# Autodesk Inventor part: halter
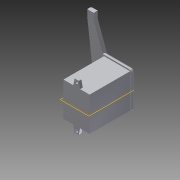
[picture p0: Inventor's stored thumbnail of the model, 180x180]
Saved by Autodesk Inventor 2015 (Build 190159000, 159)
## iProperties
Created: 2015-03
Part Number: halter
Material: PVC, hart
Document SubType Name: Modeling
Designer: Andreas
Density: 1.29 g/cm^3
Appearance: Glatt - weiß
Author: Andreas
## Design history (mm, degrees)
sketch "Skizze1"
  geometry: L1 (0, 0)-(20, 0); L2 (20, 0)-(20, -26); L3 (20, -26)-(0, -26); L4 (0, -26)-(0, 0); 3 further points
  constraints: 8 end point, 2 horizontal, 2 point on line, 1 midpoint, 1 perpendicular
  dimensions: "d1" = 26 distance of L1.end L2.end; "d2" = 20 distance of L2.end L3.end; "d3" = 26 distance of L3.end L1.start (derived); "d11" = 7.5 distance of L1.start point (7.5, 0)
extrude "Extrusion1" new body sketch "Skizze1" distance "d16" = 31; taper "d17" = 0 deg
sketch "Skizze2"
  geometry: L1 (-8.295, 5)-(-11.295, 5); L2 (-7.277, 0)-(-8.295, 5); L3 (-12.5, 0)-(-11.541, 4.799); L4 (-20, 0)-(0, 0) reference; L5 (-7.277, 0)-(-12.5, 0); A1 r 0.25 centre (-8.295, 4.75) between (-8.295, 5) and (-8.295, 5); A2 r 0.25 centre (-11.295, 4.75) between (-11.295, 5) and (-11.541, 4.799); 1 further point
  constraints: 8 end point, 4 point on circle, 3 tangent, 2 centre point, 1 collinear, 1 midpoint, 1 point on line, 1 other
  dimensions: "d18" = 3 distance of L1.start L1.end; "d19" = 5 vertical distance of L3.start L1.end; "d21" = 0.5 diameter of A2; "d26" = 7.5 distance of L4.start L3.start; "d27" = 5 vertical distance of L2.start L2.end
extrude "Extrusion2" join sketch "Skizze2" distance "d28" = 2; taper "d29" = 0 deg
fillet "Rundung1" dims "d30" = 0.5
hole "Bohrung1" diameter "d33" = 2; stored, may be unused: countersink angle "d37" = 90 deg, drill point angle "d39" = 118 deg; dims "d31" = 10, "d32" = 10, "d34" = 6, "d35" = 4, "d36" = 2, "d38" = 8
workplane "Arbeitsebene1"
mirror "Spiegeln1"
sketch "Skizze3"
  geometry: L1 (-21, -1)-(1, -1); L2 (1, -1)-(1, 27); L3 (1, 27)-(-21, 27); L4 (-21, 27)-(-21, -1); L5 (-21, 27)-(-27.84, 45.794); L6 (-21, 27)-(-1, 27); L7 (-27.84, 45.794)-(-27.84, 50.794); L8 (-27.84, 50.794)-(-32.84, 50.794); L9 (-32.84, 50.794)-(-32.84, 45.794); L10 (-32.84, 45.794)-(-28.73, 13); L11 (-28.73, 13)-(-21, 13); L12 (-32.84, -19.794)-(-28.73, 13); L13 (-21, -1)-(-27.84, -19.794); L14 (-27.84, -19.794)-(-27.84, -24.794); L15 (-27.84, -24.794)-(-32.84, -24.794); L16 (-32.84, -24.794)-(-32.84, -19.794); 2 further points
  constraints: 32 end point, 4 symmetric about line, 3 perpendicular, 2 parallel, 1 equal length, 1 horizontal, 1 midpoint, 1 vertical
  dimensions: "d42" = 28 distance of L3.end L1.start; "d43" = 22 distance of L1.start L1.end; "d44" = 20 distance of L3.end L5.end; "d45" = 110 deg angle of L6 L5; "d46" = 5 distance of L5.end L7.end; "d47" = 5 distance of L7.end L8.end; "d48" = 5 distance of L8.end L9.end
extrude "Extrusion3" join sketch "Skizze3" distance "d49" = 3; taper "d50" = 0 deg
fillet "Rundung2" dims "d51" = 2
fillet "Rundung3" dims "d52" = 2
fillet "Rundung4" dims "d53" = 2
fillet "Rundung5" dims "d54" = 2
fillet "Rundung6" dims "d55" = 2
node "Volumenkörper1"
